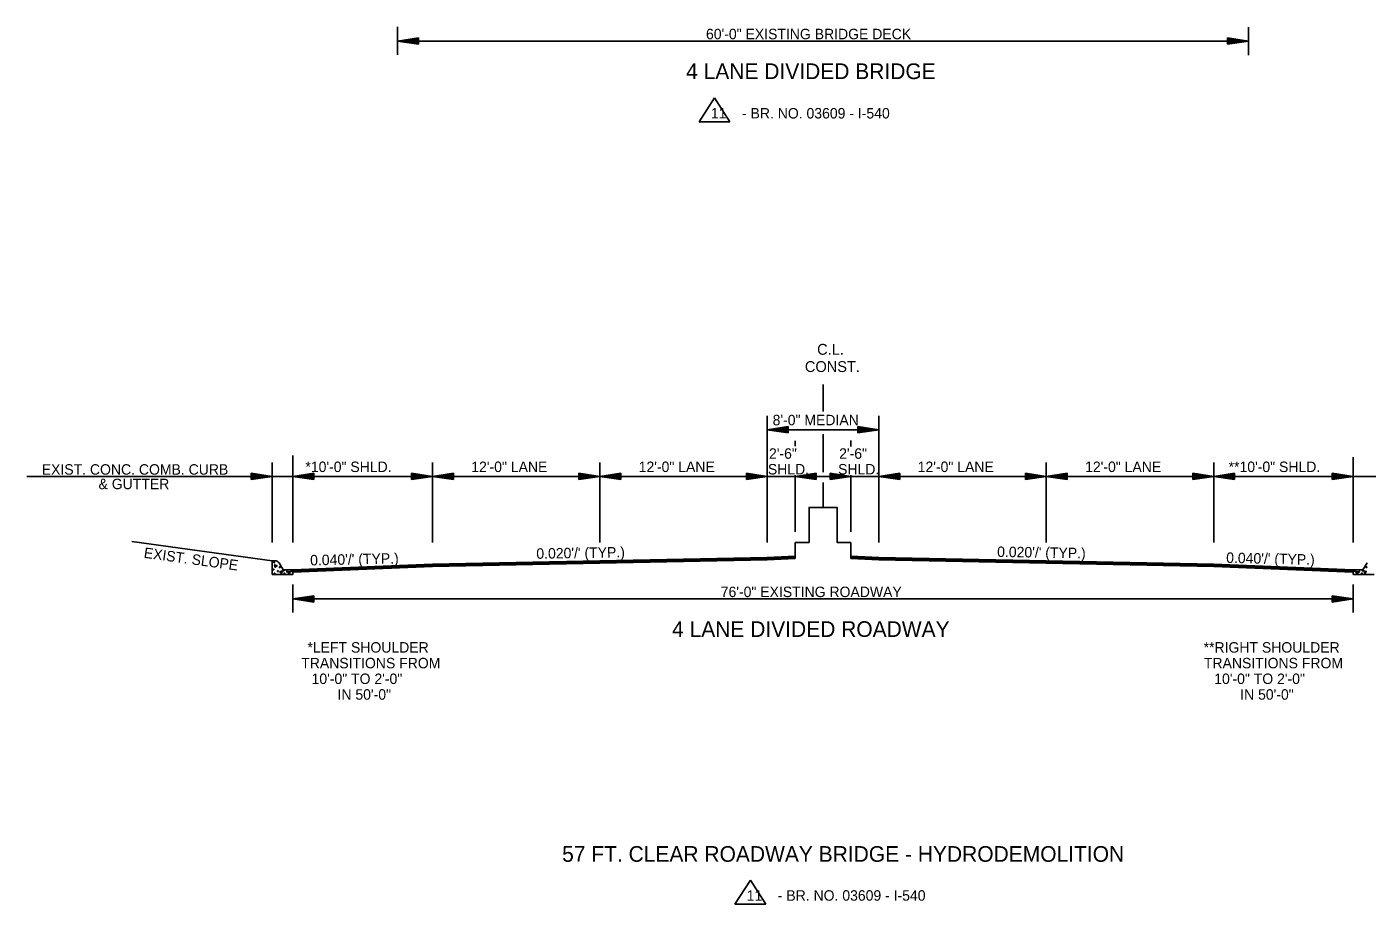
# Model space of a CAD drawing. Extents: x 542112 to 1930787, y -1968972 to 596640.
# Drawn here: x 544246 to 545207, y -1956029 to -1955400 of the extents above; entities that cross this region are included whole.
import ezdxf

# ---------------------------------------------------------------- set-up
doc = ezdxf.new("R2010")
doc.units = 0
doc.layers.add('R_Border', color=7, linetype='Continuous')
doc.layers.add('R_Draft', color=7, linetype='Continuous')

msp = doc.modelspace()

# ---------------------------------------------------------------- linework, layer by layer
at = {"layer": 'R_Border'}
for p, q in [((544739.11, -1955450.52), (544728.07, -1955467.82)), ((544750.15, -1955467.82), (544739.11, -1955450.52)), ((544728.07, -1955467.82), (544750.15, -1955467.82)), ((544764.78, -1956011.39), (544753.74, -1956028.69)), ((544775.82, -1956028.69), (544764.78, -1956011.39)), ((544753.74, -1956028.69), (544775.82, -1956028.69))]:
    msp.add_line(p, q, dxfattribs=at)
at = {"layer": 'R_Draft'}
for p, q in [((544511.83, -1955399.56), (544511.83, -1955419.56)), ((545121.83, -1955399.81), (545121.83, -1955419.81)), ((544526.83, -1955407.56), (544511.83, -1955409.81)), ((544526.83, -1955412.06), (544511.83, -1955409.81)), ((544511.83, -1955409.81), (545121.83, -1955409.81)), ((544526.83, -1955407.93), (544514.34, -1955409.81)), ((544526.83, -1955411.68), (544514.34, -1955409.81)), ((544526.83, -1955408.31), (544516.92, -1955409.81)), ((544526.83, -1955411.3), (544516.92, -1955409.81)), ((544526.83, -1955408.69), (544519.41, -1955409.81)), ((544526.83, -1955410.92), (544519.41, -1955409.81)), ((544526.83, -1955409.07), (544521.96, -1955409.81)), ((544526.83, -1955410.53), (544521.96, -1955409.81)), ((544526.83, -1955409.45), (544524.46, -1955409.81)), ((544526.83, -1955410.16), (544524.46, -1955409.81)), ((544526.83, -1955412.06), (544526.83, -1955407.56)), ((545106.83, -1955407.56), (545121.83, -1955409.81)), ((545106.83, -1955407.56), (545106.83, -1955412.06)), ((545106.83, -1955407.93), (545119.33, -1955409.81)), ((545106.83, -1955408.31), (545116.75, -1955409.81)), ((545106.83, -1955408.69), (545114.25, -1955409.81)), ((545106.83, -1955409.08), (545111.71, -1955409.81)), ((545106.83, -1955409.45), (545109.2, -1955409.81)), ((545106.83, -1955412.06), (545121.83, -1955409.81)), ((545106.83, -1955410.54), (545111.71, -1955409.81)), ((545106.83, -1955411.3), (545116.75, -1955409.81)), ((545106.83, -1955411.68), (545119.33, -1955409.81)), ((545106.83, -1955410.92), (545114.25, -1955409.81)), ((545106.83, -1955410.16), (545109.2, -1955409.81)), ((544816.98, -1955675.36), (544816.98, -1955655.96)), ((544776.91, -1955769.4), (544776.91, -1955678.56)), ((544856.91, -1955769.4), (544856.91, -1955678.56)), ((544791.91, -1955686.2), (544776.91, -1955688.45)), ((544776.91, -1955688.45), (544856.91, -1955688.45)), ((544791.91, -1955690.7), (544776.91, -1955688.45)), ((544791.91, -1955686.57), (544779.42, -1955688.45)), ((544791.91, -1955690.32), (544779.42, -1955688.45)), ((544791.91, -1955686.96), (544782, -1955688.45)), ((544791.91, -1955689.94), (544782, -1955688.45)), ((544791.91, -1955687.33), (544784.5, -1955688.45)), ((544791.91, -1955689.57), (544784.5, -1955688.45)), ((544791.91, -1955687.72), (544787.04, -1955688.45)), ((544791.91, -1955689.18), (544787.04, -1955688.45)), ((544791.91, -1955688.1), (544789.54, -1955688.45)), ((544791.91, -1955688.8), (544789.54, -1955688.45)), ((544791.91, -1955686.2), (544791.91, -1955690.7)), ((544816.91, -1955718.91), (544816.91, -1955691.56)), ((544841.91, -1955686.2), (544856.91, -1955688.45)), ((544841.91, -1955686.2), (544841.91, -1955690.7)), ((544841.91, -1955686.57), (544854.41, -1955688.45)), ((544841.91, -1955686.96), (544851.83, -1955688.45)), ((544841.91, -1955687.33), (544849.33, -1955688.45)), ((544841.91, -1955687.72), (544846.79, -1955688.45)), ((544841.91, -1955688.1), (544844.28, -1955688.45)), ((544841.91, -1955690.7), (544856.91, -1955688.45)), ((544841.91, -1955689.18), (544846.79, -1955688.45)), ((544841.91, -1955689.94), (544851.83, -1955688.45)), ((544841.91, -1955690.32), (544854.41, -1955688.45)), ((544841.91, -1955689.57), (544849.33, -1955688.45)), ((544841.91, -1955688.8), (544844.28, -1955688.45)), ((544796.91, -1955700.26), (544796.91, -1955696.46)), ((544836.91, -1955700.47), (544836.91, -1955696.08)), ((544421.93, -1955769.4), (544421.93, -1955712.09)), ((544436.91, -1955769.4), (544436.91, -1955707.03)), ((544536.91, -1955769.4), (544536.91, -1955712.09)), ((544656.91, -1955769.4), (544656.91, -1955712.09)), ((544976.91, -1955769.4), (544976.91, -1955712.09)), ((545096.91, -1955769.4), (545096.91, -1955712.09)), ((545196.91, -1955769.4), (545196.91, -1955708.05)), ((544406.9, -1955719.74), (544421.9, -1955721.99)), ((544406.9, -1955719.74), (544406.9, -1955724.24)), ((544406.9, -1955720.11), (544419.4, -1955721.99)), ((544406.9, -1955720.49), (544416.82, -1955721.99)), ((544406.9, -1955720.87), (544414.32, -1955721.99)), ((544406.9, -1955721.26), (544411.78, -1955721.99)), ((544406.9, -1955721.63), (544409.27, -1955721.99)), ((544451.91, -1955719.74), (544436.91, -1955721.99)), ((544451.91, -1955720.11), (544439.42, -1955721.99)), ((544451.91, -1955720.49), (544442, -1955721.99)), ((544451.91, -1955720.87), (544444.5, -1955721.99)), ((544451.91, -1955721.26), (544447.04, -1955721.99)), ((544451.91, -1955721.63), (544449.54, -1955721.99)), ((544451.91, -1955719.74), (544451.91, -1955724.24)), ((544521.91, -1955719.74), (544536.91, -1955721.99)), ((544521.91, -1955719.74), (544521.91, -1955724.24)), ((544521.91, -1955720.11), (544534.41, -1955721.99)), ((544521.91, -1955720.49), (544531.83, -1955721.99)), ((544521.91, -1955720.87), (544529.33, -1955721.99)), ((544521.91, -1955721.26), (544526.79, -1955721.99)), ((544521.91, -1955721.63), (544524.28, -1955721.99)), ((544551.91, -1955719.74), (544536.91, -1955721.99)), ((544551.91, -1955720.11), (544539.42, -1955721.99)), ((544551.91, -1955720.49), (544542, -1955721.99)), ((544551.91, -1955720.87), (544544.5, -1955721.99)), ((544551.91, -1955721.25), (544547.04, -1955721.99)), ((544551.91, -1955721.63), (544549.54, -1955721.99)), ((544551.91, -1955724.24), (544551.91, -1955719.74)), ((544641.91, -1955719.74), (544656.91, -1955721.99)), ((544641.91, -1955719.74), (544641.91, -1955724.24)), ((544641.91, -1955720.11), (544654.41, -1955721.99)), ((544641.91, -1955720.49), (544651.83, -1955721.99)), ((544641.91, -1955720.87), (544649.33, -1955721.99)), ((544641.91, -1955721.26), (544646.79, -1955721.99)), ((544641.91, -1955721.63), (544644.28, -1955721.99)), ((544671.91, -1955719.74), (544656.91, -1955721.99)), ((544671.91, -1955720.11), (544659.42, -1955721.99)), ((544671.91, -1955720.49), (544662, -1955721.99)), ((544671.91, -1955720.87), (544664.5, -1955721.99)), ((544671.91, -1955721.25), (544667.04, -1955721.99)), ((544671.91, -1955721.63), (544669.54, -1955721.99)), ((544671.91, -1955724.24), (544671.91, -1955719.74)), ((544761.91, -1955719.74), (544776.91, -1955721.99)), ((544761.91, -1955719.74), (544761.91, -1955724.24)), ((544761.91, -1955720.11), (544774.41, -1955721.99)), ((544761.91, -1955720.49), (544771.83, -1955721.99)), ((544761.91, -1955720.87), (544769.33, -1955721.99)), ((544761.91, -1955721.26), (544766.79, -1955721.99)), ((544761.91, -1955721.63), (544764.28, -1955721.99)), ((544811.91, -1955719.74), (544796.91, -1955721.99)), ((544796.91, -1955761.67), (544796.91, -1955721.14)), ((544811.91, -1955720.11), (544799.42, -1955721.99)), ((544811.91, -1955720.49), (544802, -1955721.99)), ((544811.91, -1955720.87), (544804.5, -1955721.99)), ((544811.91, -1955721.26), (544807.04, -1955721.99)), ((544811.91, -1955721.63), (544809.54, -1955721.99)), ((544811.91, -1955719.74), (544811.91, -1955724.24)), ((544821.91, -1955719.74), (544836.91, -1955721.99)), ((544821.91, -1955719.74), (544821.91, -1955724.24)), ((544821.91, -1955720.11), (544834.41, -1955721.99)), ((544821.91, -1955720.49), (544831.83, -1955721.99)), ((544821.91, -1955720.87), (544829.33, -1955721.99)), ((544821.91, -1955721.26), (544826.79, -1955721.99)), ((544821.91, -1955721.63), (544824.28, -1955721.99)), ((544836.91, -1955761.67), (544836.91, -1955721.05)), ((544871.91, -1955719.74), (544856.91, -1955721.99)), ((544871.91, -1955720.11), (544859.42, -1955721.99)), ((544871.91, -1955720.49), (544862, -1955721.99)), ((544871.91, -1955720.87), (544864.5, -1955721.99)), ((544871.91, -1955721.26), (544867.04, -1955721.99)), ((544871.91, -1955721.63), (544869.54, -1955721.99)), ((544871.91, -1955719.74), (544871.91, -1955724.24)), ((544961.91, -1955719.74), (544976.91, -1955721.99)), ((544961.91, -1955724.24), (544961.91, -1955719.74)), ((544961.91, -1955720.11), (544974.41, -1955721.99)), ((544961.91, -1955720.49), (544971.83, -1955721.99)), ((544961.91, -1955720.87), (544969.33, -1955721.99)), ((544961.91, -1955721.25), (544966.79, -1955721.99)), ((544961.91, -1955721.63), (544964.28, -1955721.99)), ((544991.91, -1955719.74), (544976.91, -1955721.99)), ((544991.91, -1955720.11), (544979.42, -1955721.99)), ((544991.91, -1955720.49), (544982, -1955721.99)), ((544991.91, -1955720.87), (544984.5, -1955721.99)), ((544991.91, -1955721.26), (544987.04, -1955721.99)), ((544991.91, -1955721.63), (544989.54, -1955721.99)), ((544991.91, -1955719.74), (544991.91, -1955724.24)), ((545081.91, -1955719.74), (545096.91, -1955721.99)), ((545081.91, -1955724.24), (545081.91, -1955719.74)), ((545081.91, -1955720.11), (545094.41, -1955721.99)), ((545081.91, -1955720.49), (545091.83, -1955721.99)), ((545081.91, -1955720.87), (545089.33, -1955721.99)), ((545081.91, -1955721.25), (545086.79, -1955721.99)), ((545081.91, -1955721.63), (545084.28, -1955721.99)), ((545111.91, -1955719.74), (545096.91, -1955721.99)), ((545111.91, -1955720.11), (545099.42, -1955721.99)), ((545111.91, -1955720.49), (545102, -1955721.99)), ((545111.91, -1955720.87), (545104.5, -1955721.99)), ((545111.91, -1955721.26), (545107.04, -1955721.99)), ((545111.91, -1955721.63), (545109.54, -1955721.99)), ((545111.91, -1955719.74), (545111.91, -1955724.24)), ((545181.91, -1955719.74), (545196.91, -1955721.99)), ((545181.91, -1955719.74), (545181.91, -1955724.24)), ((545181.91, -1955720.11), (545194.41, -1955721.99)), ((545181.91, -1955720.49), (545191.83, -1955721.99)), ((545181.91, -1955720.87), (545189.33, -1955721.99)), ((545181.91, -1955721.26), (545186.79, -1955721.99)), ((545181.91, -1955721.63), (545184.28, -1955721.99)), ((544436.91, -1955721.99), (544246.11, -1955721.99)), ((544406.9, -1955724.24), (544421.9, -1955721.99)), ((544406.9, -1955722.72), (544411.78, -1955721.99)), ((544406.9, -1955723.48), (544416.82, -1955721.99)), ((544406.9, -1955723.86), (544419.4, -1955721.99)), ((544406.9, -1955723.1), (544414.32, -1955721.99)), ((544406.9, -1955722.34), (544409.27, -1955721.99)), ((544536.91, -1955721.99), (544436.91, -1955721.99)), ((544451.91, -1955724.24), (544436.91, -1955721.99)), ((544451.91, -1955723.86), (544439.42, -1955721.99)), ((544451.91, -1955723.48), (544442, -1955721.99)), ((544451.91, -1955723.1), (544444.5, -1955721.99)), ((544451.91, -1955722.72), (544447.04, -1955721.99)), ((544451.91, -1955722.34), (544449.54, -1955721.99)), ((544521.91, -1955724.24), (544536.91, -1955721.99)), ((544521.91, -1955722.72), (544526.79, -1955721.99)), ((544521.91, -1955723.48), (544531.83, -1955721.99)), ((544521.91, -1955723.86), (544534.41, -1955721.99)), ((544521.91, -1955723.1), (544529.33, -1955721.99)), ((544521.91, -1955722.34), (544524.28, -1955721.99)), ((544656.91, -1955721.99), (544536.91, -1955721.99)), ((544551.91, -1955724.24), (544536.91, -1955721.99)), ((544551.91, -1955723.86), (544539.42, -1955721.99)), ((544551.91, -1955723.48), (544542, -1955721.99)), ((544551.91, -1955723.1), (544544.5, -1955721.99)), ((544551.91, -1955722.71), (544547.04, -1955721.99)), ((544551.91, -1955722.34), (544549.54, -1955721.99)), ((544641.91, -1955724.24), (544656.91, -1955721.99)), ((544641.91, -1955722.72), (544646.79, -1955721.99)), ((544641.91, -1955723.48), (544651.83, -1955721.99)), ((544641.91, -1955723.86), (544654.41, -1955721.99)), ((544641.91, -1955723.1), (544649.33, -1955721.99)), ((544641.91, -1955722.34), (544644.28, -1955721.99)), ((544776.91, -1955721.99), (544656.91, -1955721.99)), ((544671.91, -1955724.24), (544656.91, -1955721.99)), ((544671.91, -1955723.86), (544659.42, -1955721.99)), ((544671.91, -1955723.48), (544662, -1955721.99)), ((544671.91, -1955723.1), (544664.5, -1955721.99)), ((544671.91, -1955722.71), (544667.04, -1955721.99)), ((544671.91, -1955722.34), (544669.54, -1955721.99)), ((544761.91, -1955724.24), (544776.91, -1955721.99)), ((544761.91, -1955722.72), (544766.79, -1955721.99)), ((544761.91, -1955723.48), (544771.83, -1955721.99)), ((544761.91, -1955723.86), (544774.41, -1955721.99)), ((544761.91, -1955723.1), (544769.33, -1955721.99)), ((544761.91, -1955722.34), (544764.28, -1955721.99)), ((544776.91, -1955721.99), (544796.91, -1955721.99)), ((544811.91, -1955724.24), (544796.91, -1955721.99)), ((544796.91, -1955721.99), (544836.91, -1955721.99)), ((544811.91, -1955723.86), (544799.42, -1955721.99)), ((544811.91, -1955723.48), (544802, -1955721.99)), ((544811.91, -1955723.1), (544804.5, -1955721.99)), ((544811.91, -1955722.72), (544807.04, -1955721.99)), ((544811.91, -1955722.34), (544809.54, -1955721.99)), ((544816.91, -1955744.24), (544816.91, -1955726.37)), ((544821.91, -1955724.24), (544836.91, -1955721.99)), ((544821.91, -1955722.72), (544826.79, -1955721.99)), ((544821.91, -1955723.48), (544831.83, -1955721.99)), ((544821.91, -1955723.86), (544834.41, -1955721.99)), ((544821.91, -1955723.1), (544829.33, -1955721.99)), ((544821.91, -1955722.34), (544824.28, -1955721.99)), ((544856.91, -1955721.99), (544836.91, -1955721.99)), ((544871.91, -1955724.24), (544856.91, -1955721.99)), ((544856.91, -1955721.99), (544976.91, -1955721.99)), ((544871.91, -1955723.86), (544859.42, -1955721.99)), ((544871.91, -1955723.48), (544862, -1955721.99)), ((544871.91, -1955723.1), (544864.5, -1955721.99)), ((544871.91, -1955722.72), (544867.04, -1955721.99)), ((544871.91, -1955722.34), (544869.54, -1955721.99)), ((544961.91, -1955724.24), (544976.91, -1955721.99)), ((544961.91, -1955722.71), (544966.79, -1955721.99)), ((544961.91, -1955723.48), (544971.83, -1955721.99)), ((544961.91, -1955723.86), (544974.41, -1955721.99)), ((544961.91, -1955723.1), (544969.33, -1955721.99)), ((544961.91, -1955722.34), (544964.28, -1955721.99)), ((544991.91, -1955724.24), (544976.91, -1955721.99)), ((544976.91, -1955721.99), (545096.91, -1955721.99)), ((544991.91, -1955723.86), (544979.42, -1955721.99)), ((544991.91, -1955723.48), (544982, -1955721.99)), ((544991.91, -1955723.1), (544984.5, -1955721.99)), ((544991.91, -1955722.72), (544987.04, -1955721.99)), ((544991.91, -1955722.34), (544989.54, -1955721.99)), ((545081.91, -1955724.24), (545096.91, -1955721.99)), ((545081.91, -1955722.71), (545086.79, -1955721.99)), ((545081.91, -1955723.48), (545091.83, -1955721.99)), ((545081.91, -1955723.86), (545094.41, -1955721.99)), ((545081.91, -1955723.1), (545089.33, -1955721.99)), ((545081.91, -1955722.34), (545084.28, -1955721.99)), ((545096.91, -1955721.99), (545196.91, -1955721.99)), ((545111.91, -1955724.24), (545096.91, -1955721.99)), ((545111.91, -1955723.86), (545099.42, -1955721.99)), ((545111.91, -1955723.48), (545102, -1955721.99)), ((545111.91, -1955723.1), (545104.5, -1955721.99)), ((545111.91, -1955722.72), (545107.04, -1955721.99)), ((545111.91, -1955722.34), (545109.54, -1955721.99)), ((545181.91, -1955724.24), (545196.91, -1955721.99)), ((545181.91, -1955722.72), (545186.79, -1955721.99)), ((545181.91, -1955723.48), (545191.83, -1955721.99)), ((545181.91, -1955723.86), (545194.41, -1955721.99)), ((545181.91, -1955723.1), (545189.33, -1955721.99)), ((545181.91, -1955722.34), (545184.28, -1955721.99)), ((545196.91, -1955721.99), (545387.72, -1955721.99)), ((544321.41, -1955768.67), (544421.91, -1955782.49)), ((544796.91, -1955780.92), (544796.91, -1955769.25)), ((544836.91, -1955780.92), (544836.91, -1955769.25)), ((544776.91, -1955780.05), (544796.91, -1955779.25)), ((544776.91, -1955780.35), (544796.91, -1955779.55)), ((544856.91, -1955780.05), (544836.91, -1955779.25)), ((544856.91, -1955780.35), (544836.91, -1955779.55)), ((544424.08, -1955782.45), (544421.91, -1955782.49)), ((544421.91, -1955782.49), (544421.91, -1955792.34)), ((544426.9, -1955783.96), (544429.99, -1955788.85)), ((544429.99, -1955788.85), (544436.91, -1955788.85)), ((544536.91, -1955784.85), (544436.91, -1955788.85)), ((544536.91, -1955785.15), (544436.91, -1955789.15)), ((544536.91, -1955785.45), (544436.91, -1955789.45)), ((544536.91, -1955785.75), (544436.91, -1955789.75)), ((544536.91, -1955786.05), (544436.91, -1955790.05)), ((544536.91, -1955786.35), (544436.91, -1955790.35)), ((544536.91, -1955786.52), (544436.91, -1955790.52)), ((544436.91, -1955788.85), (544436.91, -1955792.34)), ((544656.9, -1955782.45), (544536.91, -1955784.85)), ((544656.91, -1955782.75), (544536.91, -1955785.15)), ((544656.91, -1955783.05), (544536.91, -1955785.45)), ((544656.92, -1955783.35), (544536.91, -1955785.75)), ((544656.93, -1955783.65), (544536.91, -1955786.05)), ((544656.93, -1955783.95), (544536.91, -1955786.35)), ((544656.93, -1955784.12), (544536.91, -1955786.52)), ((544776.91, -1955780.05), (544656.9, -1955782.45)), ((544776.91, -1955780.35), (544656.91, -1955782.75)), ((544776.91, -1955780.65), (544656.91, -1955783.05)), ((544776.91, -1955780.95), (544656.92, -1955783.35)), ((544776.91, -1955781.25), (544656.93, -1955783.65)), ((544776.91, -1955781.55), (544656.93, -1955783.95)), ((544776.91, -1955781.72), (544656.93, -1955784.12)), ((544776.91, -1955780.65), (544796.91, -1955779.85)), ((544776.91, -1955780.95), (544796.91, -1955780.15)), ((544776.91, -1955781.25), (544796.91, -1955780.45)), ((544776.91, -1955781.55), (544796.91, -1955780.75)), ((544776.91, -1955781.72), (544796.91, -1955780.92)), ((544856.91, -1955780.65), (544836.91, -1955779.85)), ((544856.91, -1955780.95), (544836.91, -1955780.15)), ((544856.91, -1955781.25), (544836.91, -1955780.45)), ((544856.91, -1955781.55), (544836.91, -1955780.75)), ((544856.91, -1955781.72), (544836.91, -1955780.92)), ((544856.91, -1955780.05), (544976.93, -1955782.45)), ((544856.91, -1955780.35), (544976.92, -1955782.75)), ((544856.91, -1955780.65), (544976.91, -1955783.05)), ((544856.91, -1955780.95), (544976.91, -1955783.35)), ((544856.91, -1955781.25), (544976.9, -1955783.65)), ((544856.91, -1955781.55), (544976.9, -1955783.95)), ((544856.91, -1955781.72), (544976.89, -1955784.12)), ((544976.89, -1955784.12), (545096.91, -1955786.52)), ((544976.9, -1955783.65), (545096.91, -1955786.05)), ((544976.9, -1955783.95), (545096.91, -1955786.35)), ((544976.91, -1955783.05), (545096.91, -1955785.45)), ((544976.91, -1955783.35), (545096.91, -1955785.75)), ((544976.92, -1955782.75), (545096.91, -1955785.15)), ((544976.93, -1955782.45), (545096.91, -1955784.85)), ((545096.91, -1955784.85), (545196.91, -1955788.85)), ((545096.91, -1955785.15), (545196.91, -1955789.15)), ((545096.91, -1955785.45), (545196.91, -1955789.45)), ((545096.91, -1955785.75), (545196.91, -1955789.75)), ((545096.91, -1955786.05), (545196.91, -1955790.05)), ((545096.91, -1955786.35), (545196.91, -1955790.35)), ((545096.91, -1955786.52), (545196.91, -1955790.52)), ((545203.84, -1955788.85), (545196.91, -1955788.85)), ((545196.91, -1955788.85), (545196.91, -1955792.34)), ((545206.93, -1955783.96), (545203.84, -1955788.85)), ((544436.91, -1955792.34), (544421.91, -1955792.34)), ((545196.91, -1955792.34), (545211.91, -1955792.34)), ((544436.91, -1955799.56), (544436.91, -1955819.56)), ((544451.91, -1955807.56), (544436.91, -1955809.81)), ((544451.91, -1955807.93), (544439.42, -1955809.81)), ((544451.91, -1955808.31), (544442, -1955809.81)), ((544451.91, -1955812.06), (544451.91, -1955807.56)), ((545181.89, -1955807.56), (545196.89, -1955809.81)), ((545181.89, -1955807.56), (545181.89, -1955812.06)), ((545181.89, -1955807.93), (545194.38, -1955809.81)), ((545181.89, -1955808.31), (545191.8, -1955809.81)), ((545196.91, -1955799.48), (545196.91, -1955819.48)), ((544436.91, -1955809.81), (545196.91, -1955809.81)), ((544451.91, -1955812.06), (544436.91, -1955809.81)), ((544451.91, -1955811.68), (544439.42, -1955809.81)), ((544451.91, -1955811.3), (544442, -1955809.81)), ((544451.91, -1955808.69), (544444.5, -1955809.81)), ((544451.91, -1955810.92), (544444.5, -1955809.81)), ((544451.91, -1955809.07), (544447.04, -1955809.81)), ((544451.91, -1955810.53), (544447.04, -1955809.81)), ((544451.91, -1955809.45), (544449.54, -1955809.81)), ((544451.91, -1955810.16), (544449.54, -1955809.81)), ((545181.89, -1955808.69), (545189.31, -1955809.81)), ((545181.89, -1955809.08), (545186.76, -1955809.81)), ((545181.89, -1955809.45), (545184.26, -1955809.81)), ((545181.89, -1955812.06), (545196.89, -1955809.81)), ((545181.89, -1955810.54), (545186.76, -1955809.81)), ((545181.89, -1955811.3), (545191.8, -1955809.81)), ((545181.89, -1955811.68), (545194.38, -1955809.81)), ((545181.89, -1955810.92), (545189.31, -1955809.81)), ((545181.89, -1955810.16), (545184.26, -1955809.81))]:
    msp.add_line(p, q, dxfattribs=at)
for points in [[(544796.91, -1955769.24), (544806.91, -1955769.24), (544806.91, -1955744.24), (544816.91, -1955744.24)], [(544836.91, -1955769.24), (544826.91, -1955769.24), (544826.91, -1955744.24), (544816.91, -1955744.24)], [(544425.85, -1955785.91), (544424.09, -1955787.05), (544423.71, -1955785.27), (544425.62, -1955785.91)], [(544428.67, -1955791.89), (544427.53, -1955790.1), (544429.29, -1955789.74), (544428.67, -1955791.63)], [(544434.32, -1955792.22), (544433.19, -1955790.43), (544434.96, -1955790.06), (544434.32, -1955791.95)], [(545199.5, -1955792.22), (545200.64, -1955790.43), (545198.86, -1955790.06), (545199.5, -1955791.95)], [(545205.16, -1955791.89), (545206.3, -1955790.1), (545204.53, -1955789.74), (545205.16, -1955791.63)]]:
    msp.add_lwpolyline(points, dxfattribs=at)
for centre in [(544422.84, -1955788.65), (544423.47, -1955783.63), (544427.4, -1955787.06), (544430.33, -1955789.39), (545203.5, -1955789.39), (545206.43, -1955787.06), (544423.66, -1955791.63), (544426.13, -1955789.92), (544430.73, -1955791.56), (544432.63, -1955790.17), (544435.56, -1955789.99), (545198.26, -1955789.99), (545201.2, -1955790.17), (545203.1, -1955791.56)]:
    msp.add_circle(centre, 0.339, dxfattribs=at)
msp.add_arc((544424.13, -1955785.71), 3.26, 32.27564, 91.11964, dxfattribs=at)

# ---------------------------------------------------------------- texts
for s, height, p in [('60\'-0" EXISTING BRIDGE DECK', 7.5, (544732.97, -1955408.49)), ('4 LANE DIVIDED BRIDGE', 11.25, (544718.74, -1955437.05)), ('11    - BR. NO. 03609 - I-540', 7.5, (544736.47, -1955465.31)), ('C.L.', 7.8, (544812.65, -1955634.73)), ('CONST.', 7.8, (544803.87, -1955647.1)), ('8\'-0" MEDIAN', 7.5, (544780.74, -1955685.28)), ('2\'-6"', 7.5, (544778.12, -1955709.29)), ('2\'-6"', 7.5, (544828.44, -1955709.29)), ('*10\'-0" SHLD.', 7.5, (544445.81, -1955718.81)), ('12\'-0" LANE', 7.5, (544564.73, -1955718.81)), ('12\'-0" LANE', 7.5, (544684.73, -1955718.81)), ('12\'-0" LANE', 7.5, (544884.73, -1955718.81)), ('12\'-0" LANE', 7.5, (545004.73, -1955718.81)), ('**10\'-0" SHLD.', 7.5, (545107.6, -1955718.81)), ('EXIST. CONC. COMB. CURB', 7.5, (544256.81, -1955720.7)), ('SHLD.', 7.5, (544777.32, -1955720.54)), ('SHLD.', 7.5, (544827.64, -1955720.54)), ('& GUTTER ', 7.5, (544297.53, -1955731.1)), ('76\'-0" EXISTING ROADWAY', 7.5, (544743.54, -1955808.49)), ('4 LANE DIVIDED ROADWAY', 11.25, (544708.64, -1955837.05)), ('*LEFT SHOULDER', 7.5, (544447.27, -1955848.3)), ('**RIGHT SHOULDER', 7.5, (545089.67, -1955848.3)), ('TRANSITIONS FROM', 7.5, (544442.82, -1955859.55)), ('TRANSITIONS FROM', 7.5, (545089.88, -1955859.55)), ('10\'-0" TO 2\'-0"', 7.5, (544450.23, -1955870.8)), ('10\'-0" TO 2\'-0"', 7.5, (545097.29, -1955870.8)), ('IN 50\'-0"', 7.5, (544468.83, -1955882.05)), ('IN 50\'-0"', 7.5, (545115.89, -1955882.05)), ('57 FT. CLEAR ROADWAY BRIDGE - HYDRODEMOLITION', 11.25, (544629.84, -1955998.29)), ('11    - BR. NO. 03609 - I-540', 7.5, (544762.13, -1956026.18))]:
    msp.add_text(s, height=height, dxfattribs=at).set_placement(p)
for s, rotation, p in [('EXIST. SLOPE', 352.16821, (544329.66, -1955780.24)), ("0.040'/' (TYP.)", 1.31838, (544449.3, -1955785.8)), ("0.020'/' (TYP.)", 0.97192, (544611.42, -1955781.04)), ("0.020'/' (TYP.)", 359.02808, (544941.63, -1955779.67)), ("0.040'/' (TYP.)", 358.68162, (545105.8, -1955783.93))]:
    msp.add_text(s, height=7.5, rotation=rotation, dxfattribs=at).set_placement(p)

doc.saveas('drawing.dxf')
